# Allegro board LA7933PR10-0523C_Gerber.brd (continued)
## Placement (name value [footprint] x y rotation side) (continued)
CC90  -  [C_0402]  95.06 40.07 180 bottom
CC91  -  [C_D2]  94.84 21.81 270 bottom
CC92  -  [C_0402]  65.05 83.68 90 bottom
CD1  -  [C_0402]  131.1 14.75 270 top
CD2  -  [C_0402]  130.62 56.2 180 top
CD3  -  [C_0402]  130.62 51.88 180 top
CD4  -  [C_0402]  130.62 58.23 180 top
CD5  -  [C_0402]  130.62 60.01 180 top
CD6  -  [C_0402]  132.37 14.76 270 top
CD7  -  [C_0603]  130.86 48.32 180 top
CD8  -  [C_0603]  128.07 51.88 180 top
CD9  -  [C_0603]  130.86 44.77 180 top
CD10  -  [C_0603]  128.07 58.74 180 top
CD11  -  [C_0603]  128.07 56.2 180 top
CD12  -  [C_0603]  128.07 44.77 180 top
CD13  -  [C_0603]  128.07 48.32 180 top
CD14  -  [C_SX]  122.87 47.67 270 top
CD15  -  [C_0402]  130.62 62.29 180 top
CD16  -  [C_0402]  130.62 61.02 180 top
CD17  -  [C_0402]  130.62 87.44 180 top
CD18  -  [C_0402]  130.62 85.41 180 top
CD19  -  [C_0402]  130.62 84.39 180 top
CD20  -  [C_0402]  130.62 86.42 180 top
CD21  -  [C_0402]  127.83 82.36 180 top
CD22  -  [C_0402]  127.81 81.09 180 top
CD23  -  [C_0402]  130.66 22.45 90 bottom
CD24  -  [C_0402]  131.68 22.44 90 bottom
CD25  -  [C_0402]  130.62 58.23 180 bottom
CD26  -  [C_0402]  127.07 58.74 180 bottom
CD27  -  [C_0402]  130.62 56.2 180 bottom
CD28  -  [C_0402]  130.62 51.88 180 bottom
CD29  -  [C_0603]  127.3 56.2 180 bottom
CD30  -  [C_0603]  127.3 60.01 180 bottom
CD31  -  [C_0603]  127.3 51.88 180 bottom
CD32  -  [C_0603]  127.3 48.32 180 bottom
CD33  -  [C_0603]  127.3 44.77 180 bottom
CD34  -  [C_0603]  130.86 48.32 180 bottom
CD35  -  [C_0603]  130.86 44.77 180 bottom
CD36  -  [C_SX]  126.34 62.85 90 top
CD37  -  [C_0402]  127.1 82.07 270 bottom
CD38  -  [C_0402]  128.12 82.07 270 bottom
CD39  -  [C_0402]  130.78 82.07 270 bottom
CD40  -  [C_0402]  129.77 82.07 270 bottom
CD41  -  [C_0402]  130.86 62.29 180 bottom
CD42  -  [C_0402]  130.62 61.02 180 bottom
CD43  -  [C_0402]  130.88 79.82 180 bottom
CD44  -  [C_0402]  130.88 78.8 180 bottom
CD45  -  [C_0402]  162.41 22.45 90 top
CD46  -  [C_0402]  165.74 47.05 0 top
CD47  -  [C_0402]  161.68 47.05 0 top
CD48  -  [C_0402]  161.68 51.63 0 top
CD49  -  [C_0402]  161.4 22.45 90 top
CD50  -  [C_0402]  161.68 58.99 0 top
CD51  -  [C_0603]  161.69 45.02 0 top
CD52  -  [C_0603]  161.44 56.96 0 top
CD53  -  [C_0603]  165.5 53.66 0 top
CD54  -  [C_0603]  161.69 49.34 0 top
CD55  -  [C_0603]  165.5 56.96 0 top
CD56  -  [C_0603]  165.5 49.34 0 top
CD57  -  [C_0603]  165.5 45.02 0 top
CD58  -  [C_SX]  191.36 64.63 90 bottom
CD59  -  [C_0402]  164.69 82.07 270 top
CD60  -  [C_0402]  163.68 82.07 270 top
CD61  -  [C_0402]  162.66 82.07 270 top
CD62  -  [C_0402]  161.64 82.07 270 top
CD63  -  [C_0402]  161.69 61.79 0 top
CD64  -  [C_0402]  161.68 60.52 0 top
CD65  -  [C_0402]  161.64 79.02 270 top
CD66  -  [C_0402]  162.96 78.55 0 top
CD67  -  [C_0402]  162.41 22.45 90 bottom
CD68  -  [C_0402]  161.39 22.49 90 bottom
CD69  -  [C_0402]  165.74 51.63 0 bottom
CD70  -  [C_0402]  161.68 54.93 0 bottom
CD71  -  [C_0402]  161.68 47.05 0 bottom
CD72  -  [C_0402]  161.68 51.63 0 bottom
CD73  -  [C_0603]  165.5 49.34 0 bottom
CD74  -  [C_0603]  165.5 45.02 0 bottom
CD75  -  [C_0603]  161.69 49.34 0 bottom
CD76  -  [C_0603]  165.5 53.66 0 bottom
CD77  -  [C_0603]  161.69 56.83 0 bottom
CD78  -  [C_0603]  165.5 56.96 0 bottom
CD79  -  [C_0603]  161.69 45.02 0 bottom
CD80  -  [C_SX]  196.44 64.63 90 bottom
CD81  -  [C_0402]  163.97 80.85 270 bottom
CD82  -  [C_0402]  162.76 80.85 270 bottom
CD83  -  [C_0402]  161.85 80.85 270 bottom
CD84  -  [C_0402]  160.92 80.85 270 bottom
CD85  -  [C_0402]  161.69 61.79 0 bottom
CD86  -  [C_0402]  161.68 60.52 0 bottom
CD87  -  [C_0402]  161.64 78.99 270 bottom
CD88  -  [C_0402]  162.96 78.51 0 bottom
CE3  -  [C_0402]  182.9 88.66 0 top
CE4  -  [C_0402]  175.11 94.59 90 top
CE6  -  [C_0805]  78.84 132.45 90 bottom
CE8  -  [C_0402]  106.02 112.11 90 bottom
CE9  -  [C_0402]  100.94 112.11 90 bottom
CH1  -  [C_0402]  64.49 111.6 90 top
CH2  -  [C_0402]  13.43 114.49 180 top
CH3  -  [C_0402]  10.74 113.35 180 top
CH4  -  [C_0402]  18.23 111.82 180 bottom
CH5  -  [C_0402]  18.01 117.25 270 bottom
CH8  -  [C_0402]  8.7 125.79 180 bottom
CH18  -  [C_0402]  23.76 133.67 0 top
CH19  -  [C_0402]  26.74 133.67 180 top
CH20  -  [C_0402]  19.06 138.61 0 top
CH21  -  [C_0402]  23.32 139.79 180 top
CH22  -  [C_0402]  21.62 137.94 180 bottom
CH23  -  [C_0402]  20.35 139.81 0 top
CH30  -  [C_0603]  33.27 121.37 0 bottom
CH31  -  [C_0402]  31.12 121.1 0 bottom
CH32  -  [C_0402]  28.31 119.67 180 bottom
CH33  -  [C_0402]  29.86 114.03 270 bottom
CH34  -  [C_0402]  24.83 128.08 180 bottom
CH35  -  [C_0402]  24.83 128.97 180 bottom
CH36  -  [C_0603]  25.39 135.24 90 bottom
CH37  -  [C_0603]  23.82 134.95 90 bottom
CH40  -  [C_0603]  46.35 115.33 270 top
CH43  -  [C_0402]  26.01 120.29 90 bottom
CH44  -  [C_0603]  34.06 119.32 0 bottom
CH45  -  [C_0402]  31.31 116.35 0 bottom
CH46  -  [C_0402]  31.29 114.76 0 bottom
CH47  -  [C_0402]  33.12 112.45 270 bottom
CH48  -  [C_0402]  25.03 118.68 0 bottom
CH49  -  [C_0402]  35.88 113.35 180 bottom
CH50  -  [C_0402]  28.13 121.1 180 bottom
CH51  -  [C_0402]  44.9 121.07 0 top
CH52  -  [C_0402]  32.15 112.44 270 bottom
CH54  -  [C_0402]  27.28 101.12 270 top
CH55  -  [C_0402]  26.34 112.35 0 bottom
CH56  -  [C_0402]  23.93 116.1 180 bottom
CH57  -  [C_0402]  25.99 109.09 270 bottom
CH58  -  [C_0603]  46.35 116.7 90 top
CH59  -  [C_0402]  26.43 115.62 90 bottom
CH60  -  [C_0402]  24.97 115.05 270 bottom
CH61  -  [C_0402]  33.56 116.29 90 bottom
CH62  -  [C_0402]  33.6 114.76 270 bottom
CH63  -  [C_0402]  11.24 117.29 180 bottom
CH64  -  [C_0805]  33.32 97.35 270 top
CH65  -  [C_0805]  35.22 97.33 270 top
CH66  -  [C_0402]  24.97 115.93 90 bottom
CH67  -  [C_0402]  26.43 114.73 270 bottom
CH68  -  [C_0402]  28.05 116.29 0 bottom
CH69  -  [C_0402]  28.04 114.4 90 bottom
CH70  -  [C_0603]  14.09 114.55 180 bottom
CH71  -  [C_0603]  10.98 123.7 180 bottom
CH72  -  [C_0402]  27.99 113.11 0 bottom
CH73  -  [C_0603]  23.77 122.29 90 bottom
CH74  -  [C_0402]  25.5 123.02 270 bottom
CH75  -  [C_0402]  25.09 120.21 180 bottom
CH76  -  [C_0402]  32.61 101.12 270 top
CH77  -  [C_0402]  30.29 118.68 180 bottom
CH78  -  [C_0402]  24.01 112.6 180 bottom
CH79  -  [C_0402]  35.02 116.73 90 bottom
CH80  -  [C_0603]  33.88 101.11 270 top
CH81  -  [C_0402]  29.82 120.24 90 bottom
CH82  -  [C_0402]  28.44 111.67 0 bottom
CH83  -  [C_0402]  24.97 113.08 270 bottom
CH84  -  [C_0402]  25.42 110.87 270 bottom
CH85  -  [C_0603]  45.11 117.16 0 bottom
CH86  -  [C_0402]  41.62 108.72 270 bottom
CH87  -  [C_0402]  40.7 108.72 270 bottom
CH88  -  [C_0402]  17.2 114.57 0 bottom
CH89  -  [C_0402]  17.24 112.75 0 bottom
CH90  -  [C_0402]  17.2 113.64 0 bottom
CH91  -  [C_0402]  22.72 120.31 180 bottom
CH92  -  [C_0402]  39.05 127.54 90 bottom
CH93  -  [C_0402]  40.47 127.47 90 bottom
CH94  -  [C_B2]  37.69 132.55 270 top
CH95  -  [C_B2]  40.99 132.55 270 top
CH96  -  [C_0402]  31.25 119.57 0 bottom
CH97  -  [C_0402]  40.81 102.64 0 bottom
CH98  -  [C_0402]  7.94 120.71 180 bottom
CH99  -  [C_0402]  18.1 97.09 180 top
CH100  -  [C_0402]  36.68 96.8 270 bottom
CH101  -  [C_0402]  11.91 126.34 90 top
CH102  -  [C_0402]  6.48 102.17 0 top
CH103  -  [C_0402]  33.64 124.35 180 bottom
CH104  -  [C_0402]  33.53 125.79 0 bottom
CH105  -  [C_0805]  44.85 126.05 0 bottom
CH106  -  [C_0603]  33.56 132.21 90 bottom
CMOS1  -  [SHORTPADS]  143.86 92.52 90 bottom
D6  -  [BAT54CW_SOT323-3]  67.6 146.53 180 bottom
D7  -  [RB751VM-40TE-17_SOD323-2]  188.57 86.9 90 top
D8  -  [RB751VM-40TE-17_SOD323-2]  192.12 86.9 90 top
D9  -  [BAT1000-7-F_SOT23-3]  73.59 165.75 180 top
D10  -  [PESD5V0U2BT_SOT23-3]  53.95 166.15 0 top
D11  -  [PESD5V0U2BT_SOT23-3]  49.88 166.15 0 top
D12  -  [BAT1000-7-F_SOT23-3]  23.98 158.79 0 top
D13  -  [PESD5V0U2BT_SOT23-3]  13.33 133.67 90 top
D14  -  [IP4292CZ10-TBR_XSON10_2P5X1]  290.15 112.29 180 bottom
D15  -  [PESD5V0U2BT_SOT23-3]  296.77 122.01 0 bottom
D16  -  [IP4292CZ10-TBR_XSON10_2P5X1]  288.44 98.3 90 top
D17  -  [PESD5V0U2BT_SOT23-3]  288.64 93.79 90 top
D18  -  [RB751VM-40TE-17_SOD323-2]  190.35 86.9 90 top
D19  -  [RB751VM-40TE-17_SOD323-2]  198 150.91 0 bottom
D28  -  [RB751S40T1_SOD523-2]  298.68 110.35 270 bottom
D29  -  [RB751S40T1_SOD523-2]  186.92 101.66 270 bottom
D30  -  [RB751S40T1_SOD523-2]  177.01 86.42 90 bottom
D31  -  [RB751S40T1_SOD523-2]  191.87 102.87 270 bottom
D32  -  [RB751S40T1_SOD523-2]  117.19 126.11 90 top
D33  -  [PESD24VS2UT_SOT23-3]  75.79 135.22 0 bottom
D34  -  [RB751S40T1_SOD523-2]  249.47 69.15 180 bottom
D53  -  [RB751VM-40TE-17_SOD323-2]  69.95 147.67 270 bottom
D59  -  [RB751S40T1_SOD523-2]  234.35 60.77 0 bottom
D60  -  [RB751S40T1_SOD523-2]  228.45 63.76 270 bottom
D62  -  [RB751S40T1_SOD523-2]  235.56 63.76 270 bottom
D63  -  [RB751S40T1_SOD523-2]  229.97 63.76 270 bottom
D64  -  [RB751VM-40TE-17_SOD323-2]  82.87 140.02 0 top
D66  -  [RB751VM-40TE-17_SOD323-2]  80.91 136.46 180 top
D67  -  [RB751VM-40TE-17_SOD323-2]  82.87 136.46 0 top
D68  -  [RB751VM-40TE-17_SOD323-2]  85.1 130.24 180 top
D69  -  [RB751VM-40TE-17_SOD323-2]  82.87 138.24 0 top
D70  -  [RB751V-40GTE-17_SOD323-2]  37.4 163.64 0 top
D71  -  [RB751VM-40TE-17_SOD323-2]  83.16 138.78 270 bottom
D73  -  [PESD5V0U2BT_SOT23-3]  9.75 164.68 180 top
D86  -  [PESD5V0U2BT_SOT23-3]  4.67 121.88 180 top
D87  -  [PESD5V0U2BT_SOT23-3]  13.33 137.73 90 top
D90  -  [RB751S40T1_SOD523-2]  222.39 89.4 270 bottom
D103  -  [RB751S40T1_SOD523-2]  164.31 104.21 90 bottom
DH2  -  [RB751S40T1_SOD523-2]  11.21 118.68 180 bottom
DH3  -  [RB751S40T1_SOD523-2]  11.16 122.24 180 bottom
F3  -  [F_1206L150PR]  290.55 136.46 180 top
F4  -  [F_SMD1812P200TF]  32.78 158.8 180 top
F5  -  [F_SMD1812P200TF]  77.14 168.97 180 top
FD1  -  [FIDUCIAL_C40M80]  290.17 14.54 0 top
FD2  -  [FIDUCIAL_C40M80]  7.21 166.69 0 top
FD3  -  [FIDUCIAL_C40M80]  290.17 14.54 180 bottom
FD4  -  [FIDUCIAL_C40M80]  7.72 167.2 180 bottom
H1  -  [H_3P0]  296.49 169.7 0 top
H2  -  [H_3P6]  297.09 77.8 0 top
H3  -  [H_3P6]  220.49 77.8 0 top
H4  -  [H_3P0]  291.89 7.03 0 top
H5  -  [H_3P0]  270.89 87.13 0 top
H6  -  [H_3P6]  297.09 16.1 0 top
H7  -  [H_3P6]  220.49 16.1 0 top
H8  -  [H_5P2]  212.78 98.05 0 top
H9  -  [H_3P0]  198.39 26.03 0 top
H10  -  [H_3P0]  166.29 169.2 0 top
H11  -  [H_3P8]  136.89 170.77 0 top
H12  -  [H_3P8]  136.89 95.77 0 top
H13  -  [H_3P0]  123.29 7.43 0 top
H14  -  [H_3P0]  115.89 12.23 0 top
H15  -  [H_4P2]  104.19 87.4 0 top
H16  -  [H_4P2]  104.19 33.2 0 top
H17  -  [H_3P0]  60.49 167.7 0 top
H18  -  [H_4P2]  58.19 87.4 0 top
H19  -  [H_4P2]  55.19 33.2 270 top
H20  -  [H_3P0]  3.49 162.2 0 top
H21  -  [H_4P2N]  48.09 33.2 0 top
H22  -  [H_1P2]  73.37 157.91 180 bottom
H23  -  [H_1P2]  56.61 144.91 180 bottom
H24  -  [H_1P2]  41.61 157.91 180 bottom
H25  -  [H_1P2]  88.37 144.91 180 bottom
H26  -  [H_3P0X3P6]  293.29 159.2 90 top
JBT1  -  [ACES_50228-0127N-001_12P]  302.56 106.44 0 top
JCAM1  -  [ACES_50238-0207N-002_20P-T]  7.09 125.2 90 top
JCPU1  -  [TYCO_2134146-3_989P]  99.9 41.45 90 top
JCRT1  -  [SUYIN_070449HR015M221ZR_15P-T]  56.5 173.96 0 top
JDEG2  -  [ACES_87153-10411_10P]  211.91 108.94 90 top
JDIMM1  -  [TYCO_2-2013311-1_204P]  143.09 20.5 270 top
JDIMM2  -  [TYCO_2-2013290-1_204P]  134.89 20.5 270 bottom
JDIMM3  -  [TYCO_2-2013290-1_204P]  157.29 20.5 270 top
JDIMM4  -  [TYCO_2-2013289-1_204P]  149.09 20.5 270 bottom
JDOCK1  -  [JAE_WD2F144WB5R400_144P-T]  81.74 118.7 0 bottom
JDP1  -  [FOX_3V1121C-N1YD7-7H_20P-T]  293.78 150.25 90 top
JEDP1  -  [ACES_50398-04071-001_40P]  67.24 156.4 0 top
JESA1  -  [FOX_3Q38111-C35C5B-7H_11P-T]  14.49 170.97 180 top
JFAN1  -  [ACES_50271-0040N-001_4P]  11.15 84.9 90 bottom
JFAN2  -  [ACES_50271-0040N-001_4P]  225.91 79.82 315 bottom
JHDMI1  -  [FOX_QJ1119L-BT11-7H_19P-T]  27.95 168.29 180 top
JIO1  -  [FOX_QTS01401-A021-9H_140P-T]  31.01 45.55 90 top
JKB1  -  [AMPHE_G281010112CHR_10P]  80.75 111.25 0 top
JLOM1  -  [TYCO_2041333-1_13P]  84.22 162.27 180 top
JLVDS1  -  [ACES_50398-04071-001_40P]  82.24 143.39 0 top
JMINI1  -  [BELLW_80003-1121_52P]  99.84 140.25 90 bottom
JMINI2  -  [LCN_DAN08-52526-0100_52P]  202.29 90.36 180 bottom
JMINI3  -  [LCN_DAN08-52526-0100_52P]  169.84 165.18 0 bottom
JMINI4  -  [LCN_DAN08-52526-0100_52P]  9.64 157.75 0 bottom
JMXM1  -  [JAE_MM70-314-310B1-1-_310P-S]  197.69 173.27 270 top
JODD1  -  [FOX_LN21131-D008-9H_13P-T]  24.27 41.63 270 top
JPB1  -  [ACES_50228-0067N-001_6P]  276.49 90.98 180 top
JRTC1  -  [ACES_50271-0020N-001_2P]  51.92 99.76 270 bottom
JSATA1  -  [SUYIN_127043HB022M26GZL_22P-T]  200.42 35.91 90 top
JSATA2  -  [SUYIN_127043HB022M26GZL_22P-T]  64 32.16 0 top
JSIM1  -  [SUYIN_254070FB008S205ZL_8P]  263.56 28.9 180 bottom
JSPI1  -  [TYCO_1-2041070-6_16P]  48.97 104.26 270 bottom
JTAG1  -  [SHORTPADS]  167.74 157.8 90 top
JUSB1  -  [LOTES_AUSB0041-P001A_9P-T]  293.26 116.34 90 top
JUSB2  -  [LOTES_AUSB0041-P001A_9P-T]  293.26 93.25 90 top
JUSH1  -  [ACES_50554-02001-001_20P-T]  117.89 36.8 270 top
JWL1  -  [ACES_50228-0037N-001_3P-T]  283.62 7.24 180 top
JXDP1  -  [MOLEX_52435-2671_26P-T]  68.65 91.43 0 bottom
JXDP2  -  [SAMTE_BSH-030-01-L-D-A_60P]  76.56 108.59 180 top
L1  -  [MURAT_BLM18PG330SN1D_2P]  48.27 160.34 0 bottom
L2  -  [MURAT_BLM18PG330SN1D_2P]  52.08 160.34 0 bottom
L3  -  [MURAT_BLM18PG330SN1D_2P]  55.13 160.34 0 bottom
L4  -  [MURAT_BLM18AG121SN1D_L0603_2P]  66.39 166.85 90 top
L5  -  [MURAT_BLM18AG121SN1D_L0603_2P]  68.93 166.85 90 top
L10  -  [MURAT_DLW21SN121SQ2L_4P]  17.13 137.33 180 top
L11  -  [MURAT_DLW21SN121SQ2L_4P]  6.59 117.14 180 top
L19  -  [MURAT_DLW21SN900HQ2L_0805_4P]  33.8 162.41 90 top
L23  -  [MURAT_DLW21SN900HQ2L_0805_4P]  31.77 162.41 90 top
L24  -  [MURAT_DLW21SN900HQ2L_0805_4P]  29.74 162.41 90 top
L25  -  [MURAT_DLW21SN900HQ2L_0805_4P]  27.7 162.41 90 top
L29  -  [TAIYO_CBC2012T4R7M_2P]  118.71 159.7 180 top
L30  -  [DELTA_0603CS-120EJTS_2P]  118.97 150.06 270 top
L31  -  [DELTA_0603CS-120EJTS_2P]  120.5 150.06 270 top
L32  -  [DELTA_0603CS-120EJTS_2P]  123.54 150.06 270 top
L33  -  [DELTA_0603CS-120EJTS_2P]  122.02 150.06 270 top
L34  -  [DELTA_0603CS-120EJTS_2P]  125.07 150.06 270 top
L35  -  [DELTA_0603CS-120EJTS_2P]  126.59 150.06 270 top
L36  -  [DELTA_0603CS-120EJTS_2P]  128.12 150.06 270 top
L37  -  [DELTA_0603CS-120EJTS_2P]  129.64 150.06 270 top
L39  -  [MURAT_DLW21SN900SQ2L_0805_4P]  297.53 117.78 270 bottom
L40  -  [MURAT_DLW21SN900HQ2L_0805_4P]  288.54 110.39 270 bottom
L41  -  [CHENG_OCE2012120YZF_4P]  284.08 94.59 180 top
L42  -  [MURAT_DLW21SN900HQ2L_0805_4P]  290.57 110.39 270 bottom
L43  -  [MURAT_DLW21SN900HQ2L_0805_4P]  285.02 100.08 180 top
L44  -  [MURAT_DLW21SN900HQ2L_0805_4P]  285.04 97.75 180 top
L51  -  [MURAT_DLW21SN900SQ2L_0805_4P]  10.18 158.85 90 top
LH1  -  [TDK_GLFR1608T1R0M-LR_2P]  26.8 136.7 270 bottom
LH3  -  [TAIYO_LBR2012T100M_2P]  49.39 117.16 180 top
LH5  -  [TAIYO_LBR2012T100M_2P]  35.66 101.14 270 top
LH6  -  [TAIYO_LBR2012T100M_2P]  34.9 133.15 270 top
LH7  -  [TAIYO_LBR2012T100M_2P]  43.79 133.15 270 top
LH8  -  [TAIYO_HK1608R10J-T_L0603_2P]  46.22 127.83 180 bottom
ME1  -  [SHORTPADS]  142.59 92.52 90 bottom
NOREF  -  []  58.19 87.4 0 top
NOREF#2  -  []  104.19 33.2 0 top
NOREF#3  -  []  297.09 77.8 0 top
NOREF#4  -  []  296.49 169.7 0 top
NOREF#5  -  []  35.91 -39.81 0 top
NOREF#6  -  []  220.49 77.8 0 top
NOREF#7  -  []  104.19 87.4 0 top
NOREF#8  -  []  166.29 169.2 0 top
NOREF#9  -  []  220.49 16.1 0 top
NOREF#10  -  []  41.76 14.29 0 top
NOREF#11  -  []  291.89 7.03 0 top
NOREF#12  -  []  123.29 7.43 0 top
NOREF#13  -  []  270.89 87.13 0 top
NOREF#14  -  []  212.78 98.05 0 top
NOREF#15  -  []  136.89 170.77 0 top
NOREF#16  -  []  293.29 159.2 0 top
NOREF#17  -  []  55.19 33.2 0 top
NOREF#18  -  []  60.49 167.7 0 top
NOREF#19  -  []  41.61 157.91 0 top
NOREF#20  -  []  88.37 144.91 0 top
NOREF#21  -  []  236.83 31.46 0 top
NOREF#22  -  []  297.09 16.1 0 top
NOREF#23  -  []  265.28 27.1 0 top
NOREF#24  -  []  56.61 144.91 0 top
NOREF#25  -  []  3.49 162.2 0 top
NOREF#26  -  []  136.89 95.77 0 top
NOREF#27  -  []  198.39 26.03 0 top
NOREF#28  -  []  73.37 157.91 0 top
NOREF#29  -  []  90.46 104.14 0 top
NOREF#30  -  []  109.32 87.88 0 top
NOREF#31  -  []  115.89 12.23 90 top
NOREF#32  -  []  15.34 248.22 0 top
NOREF#33  -  []  125.7 111.13 180 bottom
NOREF#34  -  []  102.97 93.92 180 bottom
NOREF#35  -  []  112.41 81.81 180 bottom
PBATT1  -  [SUYIN_200045GR009M28QL_9P-T]  189.34 2.65 0 top
PC1  -  [C_25CE100AX]  188.97 51.12 270 top
PC2  -  [C_0603]  43.25 98.32 90 bottom
PC3  -  [C_0603]  191.11 6.21 90 top
PC4  -  [C_0402]  190.89 8.95 0 top
PC5  -  [C_0402]  210.41 7.72 90 top
PC6  -  [C_0402]  171.87 174.32 180 top
PC7  -  [C_0603]  130.2 123.25 0 top
PC8  -  [C_0603]  133.5 118.94 0 top
PC9  -  [C_0805]  15.91 75.43 180 top
PC10  -  [C_0603]  9.24 79.26 270 top
PC11  -  [C_0603]  14.33 60.69 270 top
PC12  -  [C_0603]  5.94 79.26 270 top
PC13  -  [C_0603]  7.47 79.26 270 top
PC14  -  [C_0805]  4.37 78.93 180 top
PC15  -  [C_0603]  17.75 71.95 0 top
PC16  -  [C_0402]  135.31 124.18 180 top
PC17  -  [C_0402]  159.37 174.54 90 top
PC18  -  [C_0402]  175.8 175.72 0 bottom
PC19  -  [C_0402]  161.38 173.62 0 top
PC20  -  [C_0402]  177.77 171.02 0 bottom
PC21  -  [C_0402]  175.84 168.15 0 bottom
PC30  -  [C_0805]  186.36 172 180 top
PC31  -  [C_0603]  186.1 173.75 180 top
PC100  -  [C_0603]  281.58 58.23 0 bottom
PC101  -  [C_0603]  275.82 64.28 90 bottom
PC102  -  [C_0402]  272.39 51.59 270 bottom
PC103  -  [C_0402]  279.79 53.4 0 bottom
PC104  -  [C_0805]  269.85 52.08 270 bottom
PC105  -  [C_0805]  281.58 61.79 0 bottom
PC106  -  [C_0402]  279.79 54.42 0 bottom
PC107  -  [C_0402]  271.37 51.59 270 bottom
PC108  -  [C_0805]  276.2 52.08 270 bottom
PC109  -  [C_0805]  274.17 52.08 270 bottom
PC110  -  [C_0603]  269.9 58.99 0 bottom
PC112  -  [C_MP6VLPS220MC4R2]  284.33 34.86 0 bottom
PC113  -  [C_MP6VLPS220MC4R2]  250.38 51.58 270 bottom
PC114  -  [C_0603]  275.69 43.29 90 bottom
PC115  -  [C_0603]  269.39 44.39 0 bottom
PC116  -  [C_0603]  277.93 53.91 180 bottom
PC117  -  [C_0805]  273.86 55.69 180 bottom
PC118  -  [C_0603]  275.23 55.69 0 bottom
PC119  -  [C_0603]  264.26 64.38 90 bottom
PC120  -  [C_0402]  277.25 65.34 0 bottom
PC121  -  [C_0402]  273.44 65.34 0 bottom
PC198  -  [C_0402]  269.51 46.4 90 bottom
PC199  -  [C_0402]  274.32 48.57 180 bottom
PC201  -  [C_0805]  219.58 32.45 0 bottom
PC202  -  [C_0805]  219.58 30.41 0 bottom
PC203  -  [C_0402]  214.43 35.51 180 bottom
PC204  -  [C_0402]  214.43 34.5 180 bottom
PC205  -  [C_0603]  227.6 43.24 180 bottom
PC206  -  [C_0805]  229.32 51.92 0 bottom
PC207  -  [C_0805]  229.32 49.88 0 bottom
PC208  -  [C_0603]  230.29 40.57 0 bottom
PC209  -  [C_MP2VLPS330MC4R2]  213.96 57.72 180 bottom
PC210  -  [C_0402]  232.62 49.63 90 bottom
PC211  -  [C_0603]  233.09 40.57 0 bottom
PC212  -  [C_0603]  228.46 31.64 180 bottom
PC213  -  [C_0402]  234.94 45.53 0 bottom
PC214  -  [C_0402]  239.01 46.55 0 bottom
PC215  -  [C_0402]  239.23 51.66 90 bottom
PC216  -  [C_0402]  239.01 37.91 0 bottom
PC217  -  [C_0402]  239.99 43.28 90 bottom
PC218  -  [C_0402]  244.31 43.28 90 bottom
PC299  -  [C_0402]  222.65 33.85 0 bottom
PC301  -  [C_0805]  106.35 16.45 180 bottom
PC302  -  [C_0402]  110.3 20.89 180 bottom
PC303  -  [C_0805]  98.27 15.38 270 bottom
PC304  -  [C_0805]  100.3 15.38 270 bottom
PC305  -  [C_0402]  107.98 22.06 90 bottom
PC306  -  [C_0603]  104.49 13.32 90 bottom
PC307  -  [C_0805]  212.71 71.76 180 bottom
PC308  -  [C_0402]  215.21 74.49 180 bottom
PC309  -  [C_0805]  202.31 75.55 90 bottom
PC310  -  [C_0805]  202.31 73.93 270 bottom
PC311  -  [C_0402]  210.92 76.74 90 bottom
PC312  -  [C_0603]  210.8 68.6 90 bottom
PC401  -  [C_0402]  12.93 144.3 270 bottom
PC402  -  [C_0402]  13.94 144.3 270 bottom
PC403  -  [C_0805]  11.53 144.79 270 bottom
PC404  -  [C_0805]  9.5 146.32 270 bottom
PC405  -  [C_0603]  4.93 150.38 270 top
PC406  -  [C_D2]  11.78 141.9 90 top
PC407  -  [C_0402]  5.43 156.18 90 top
PC408  -  [C_0603]  2.64 150.38 270 top
PC409  -  [C_0603]  11.01 139.15 90 bottom
PC499  -  [C_0402]  8.81 140.42 0 bottom
PC501  -  [C_0402]  61.37 16.76 90 bottom
PC502  -  [C_0402]  60.36 16.78 90 bottom
PC503  -  [C_0805]  62.86 16.68 90 bottom
PC504  -  [C_0805]  64.77 16.57 90 bottom
PC505  -  [C_0603]  63.42 23.71 270 bottom
PC506  -  [C_0603]  62.97 24.91 90 bottom
PC507  -  [C_0402]  56.46 22.42 180 bottom
PC508  -  [C_MP2VLPS330MC4R2]  71.73 26.73 0 bottom
PC509  -  [C_0603]  65.02 22.57 270 bottom
PC510  -  [C_0402]  51.94 25.72 270 bottom
PC511  -  [C_0402]  53.47 22.16 0 bottom
PC599  -  [C_0402]  65.62 19.67 180 bottom
PC601  -  [C_0603]  49.38 22.47 90 bottom
PC602  -  [C_0603]  52.21 22.29 180 bottom
PC603  -  [C_0603]  45.57 18.56 270 bottom
PC604  -  [C_0805]  38.75 29.76 0 bottom
PC605  -  [C_0805]  38.75 25.69 0 bottom
PC606  -  [C_0402]  47.03 27.23 270 bottom
PC607  -  [C_0805]  38.8 27.72 0 bottom
PC608  -  [C_0805]  38.75 31.79 0 bottom
PC609  -  [C_0402]  45.76 27.21 270 bottom
PC610  -  [C_0805]  44.5 27.72 180 bottom
PC611  -  [C_0805]  44.5 25.69 180 bottom
PC612  -  [C_0402]  57.25 18.32 270 bottom
PC613  -  [C_0402]  58.27 18.32 270 bottom
PC614  -  [C_0805]  55.73 16.88 90 bottom
PC615  -  [C_0805]  53.69 16.88 90 bottom
PC616  -  [C_0603]  38.07 14.33 270 bottom
PC617  -  [C_0402]  49.9 13.58 0 bottom
PC618  -  [C_0402]  49.9 12.62 0 bottom
PC619  -  [C_0402]  47.85 12.54 90 bottom
PC701  -  [C_0402]  25.63 80.62 90 bottom
PC702  -  [C_0402]  26.52 84.93 90 bottom
PC703  -  [C_0402]  25.47 87.44 180 top
PC704  -  [C_0402]  24.48 84.43 90 top
PC705  -  [C_0402]  24.52 85.41 0 bottom
PC706  -  [C_0402]  24.74 80.62 90 bottom
PC707  -  [C_0402]  22.17 81.09 180 bottom
PC708  -  [C_0402]  22.91 83.63 180 bottom
PC709  -  [C_0402]  22.17 82.11 180 bottom
PC710  -  [C_0603]  40.61 43.76 270 bottom
PC711  -  [C_0402]  23.21 83.16 90 top
PC712  -  [C_0603]  45.11 46.8 0 bottom
PC713  -  [C_0805]  39.27 49.94 90 top
PC714  -  [C_0805]  48.04 46.71 180 top
PC715  -  [C_0805]  49.5 48.99 90 bottom
PC716  -  [C_0603]  43.66 48.93 90 bottom
PC717  -  [C_0402]  40.23 48.91 90 bottom
PC718  -  [C_0402]  19.97 82.93 180 bottom
PC719  -  [C_0402]  22.17 82.11 180 top
PC720  -  [C_0402]  22.17 81.09 180 top
PC721  -  [C_0603]  40.11 53.02 270 bottom
PC722  -  [C_0603]  32.13 78.96 0 top
PC723  -  [C_0603]  29.13 79.44 180 bottom
PC724  -  [C_EEEFK1E101YP]  27.82 57.04 90 top
PC725  -  [C_EEEFK1E101YP]  43.32 40.96 0 top
PC726  -  [C_EEEFK1E101YP]  20.47 59.86 90 top
PC727  -  [C_0805]  34.91 71.07 90 top
PC728  -  [C_0805]  35.05 76.16 90 top
PC729  -  [C_0805]  36.47 76.31 0 bottom
PC730  -  [C_0402]  37.09 68.9 0 bottom
PC731  -  [C_0603]  36.85 70.17 0 bottom
PC732  -  [C_0402]  19.88 77.03 180 top
PC733  -  [C_0402]  22.25 72.93 270 bottom
PC734  -  [C_0603]  33.58 81.09 180 top
PC735  -  [C_0402]  29.03 73.97 270 top
PC736  -  [C_0402]  28.24 76.85 180 bottom
PC737  -  [C_0603]  41.63 75.47 90 bottom
PC738  -  [C_0402]  23.21 72.93 270 top
PC739  -  [C_0402]  24.23 72.93 270 top
PC740  -  [C_0402]  18.9 78.9 270 top
PC741  -  [C_0402]  28.55 75.72 270 bottom
PC742  -  [C_0402]  25.25 72.93 270 top
PC743  -  [C_0402]  26.19 72.98 270 top
PC744  -  [C_0805]  34.92 65.23 90 top
PC745  -  [C_0805]  34.94 59.32 90 top
PC746  -  [C_0805]  36.6 64.45 0 bottom
PC747  -  [C_0603]  36 61.23 0 bottom
PC748  -  [C_0402]  35.82 58.79 0 bottom
PC749  -  [C_0402]  27.4 71.11 180 top
PC750  -  [C_0402]  30.33 73.44 270 bottom
PC751  -  [C_0402]  28.32 73.45 270 bottom
PC752  -  [C_0402]  29.31 73.44 270 bottom
PC753  -  [C_0402]  26.29 76.84 90 bottom
PC754  -  [C_0603]  33.55 77.36 180 top
PC755  -  [C_0402]  25.25 71.98 90 bottom
PC756  -  [C_0402]  23.21 71.98 90 bottom
PC757  -  [C_0603]  41.76 64.81 90 bottom
PC758  -  [C_0805]  36.17 92.2 0 top
PC759  -  [C_0805]  36.35 88.5 0 bottom
PC761  -  [C_0603]  36.89 90.4 0 bottom
PC762  -  [C_0402]  36.71 84.89 0 bottom
PC763  -  [C_0603]  33.53 87.35 270 top
PC764  -  [C_0603]  28.6 90.36 0 top
PC765  -  [C_0603]  40.94 90.16 180 bottom
PC766  -  [C_0805]  36.42 81.9 0 bottom
PC767  -  [C_0805]  34.94 83.06 90 top
PC769  -  [C_0603]  36.47 83.68 0 bottom
PC770  -  [C_0402]  37.18 78.34 0 bottom
PC771  -  [C_0603]  28.55 85.61 270 top
PC772  -  [C_0603]  41.63 83.88 270 bottom
PC791  -  [C_0402]  51.03 52.61 90 bottom
PC792  -  [C_0402]  45.07 53.75 90 bottom
PC793  -  [C_0402]  43.13 72.06 90 bottom
PC794  -  [C_0402]  41.84 69.17 270 bottom
PC795  -  [C_0402]  42.95 58.44 270 bottom
PC796  -  [C_0402]  41.81 61.29 90 bottom
PC797  -  [C_0402]  41.34 86.11 0 bottom
PC798  -  [C_0402]  41.9 81.16 270 bottom
PC901  -  [C_0603]  6.45 100.85 270 top
PC902  -  [C_0402]  199.11 44.93 90 bottom
PC903  -  [C_0603]  196.7 44.69 90 bottom
PC904  -  [C_0402]  171.33 37.4 0 top
PC905  -  [C_0402]  173.11 36.13 0 top
PC906  -  [C_0402]  173.36 37.4 0 top
PC907  -  [C_0805]  181.25 33.85 0 top
PC908  -  [C_0603]  175.61 37.45 90 top
PC909  -  [C_0402]  171.52 33.85 180 top
PC910  -  [C_0603]  181.13 39.31 0 top
PC911  -  [C_0603]  181.51 32.07 0 top
PC912  -  [C_0402]  198.09 44.93 90 bottom
PC913  -  [C_0603]  190.85 44.56 90 bottom
PC914  -  [C_0805]  194.66 44.31 90 bottom
PC915  -  [C_0805]  192.63 44.31 90 bottom
PC916  -  [C_0402]  176.38 26.95 270 top
PC917  -  [C_0402]  179.93 37.44 90 top
PC918  -  [C_0402]  168.28 28 0 top
PC919  -  [C_0402]  187.3 42.7 270 bottom
PC920  -  [C_0402]  168.25 30.26 270 top
PC921  -  [C_0402]  169.26 30.26 270 top
PC922  -  [C_0402]  173.84 26.95 270 top
PC923  -  [C_0402]  169.26 31.34 90 top
PC924  -  [C_0603]  172.01 32.58 180 top
PC925  -  [C_0603]  195.17 33.01 90 bottom
PC926  -  [C_0402]  170.57 28 0 top
PC927  -  [C_0402]  168.25 31.34 90 top
PC928  -  [C_0402]  171.52 25.97 180 top
PC929  -  [C_0603]  189.38 22.92 0 top
PC930  -  [C_0805]  189.38 26.73 0 top
PC931  -  [C_0805]  189.38 28.77 0 top
PC932  -  [C_0805]  189.38 24.7 0 top
PC933  -  [C_0402]  184.22 30.8 180 top
PC934  -  [C_0603]  181.71 30.24 270 top
PC935  -  [C_0402]  183.27 27.75 0 top
PC936  -  [C_0402]  236.43 16 0 bottom
PC937  -  [C_0402]  236.43 14.99 0 bottom
PC938  -  [C_0402]  229.76 21.35 180 bottom
PC939  -  [C_0402]  229.76 20.08 180 bottom
PC940  -  [C_0402]  237.89 22.61 180 bottom
PC941  -  [C_0402]  239.49 21.07 0 bottom
PC942  -  [C_0402]  249.06 18.05 180 bottom
PC999  -  [C_0402]  193.91 34.39 90 bottom
PC1001  -  [C_0805]  133.65 105.04 180 bottom
PC1002  -  [C_0402]  143.36 107.22 270 bottom
PC1003  -  [C_0603]  144.75 107.2 270 bottom
PC1004  -  [C_0805]  179.12 20.38 180 top
PC1005  -  [C_0603]  200.51 15.05 0 bottom
PC1006  -  [C_0603]  173.84 66.82 270 top
PC1007  -  [C_0603]  175.61 66.82 270 top
PC1008  -  [C_0603]  181.76 70.68 0 top
PC1009  -  [C_0402]  182 71.95 0 top
PC1101  -  [C_0805]  80.92 57.72 0 top
PC1102  -  [C_0805]  77.44 52.52 0 bottom
PC1103  -  [C_0805]  80.92 55.56 0 top
PC1104  -  [C_0805]  59.99 47.74 180 top
PC1105  -  [C_0805]  77.44 54.42 0 bottom
PC1106  -  [C_0805]  77.44 66.99 0 bottom
PC1107  -  [C_0805]  77.44 56.58 0 bottom
PC1108  -  [C_0805]  77.44 58.74 0 bottom
PC1109  -  [C_0805]  77.44 60.9 0 bottom
PC1110  -  [C_0805]  77.44 63.06 0 bottom
PC1111  -  [C_0805]  77.44 65.09 0 bottom
PC1112  -  [C_0805]  82.02 66.05 270 top
PC1113  -  [C_0805]  83.92 66.05 270 top
PC1114  -  [C_0805]  82.02 66.05 270 bottom
PC1115  -  [C_0805]  83.92 66.05 270 bottom
PC1116  -  [C_0805]  86.21 81.9 90 top
PC1117  -  [C_0805]  80.11 81.9 90 top
PC1118  -  [C_0805]  79.22 79.87 90 bottom
PC1119  -  [C_0805]  78.08 81.9 90 top
PC1120  -  [C_0805]  79.37 58.74 180 top
PC1121  -  [C_0805]  82.85 59.88 180 top
PC1122  -  [C_0805]  58.06 63.61 0 top
PC1123  -  [C_0805]  82.85 62.04 180 top
PC1124  -  [C_0805]  58.06 52.18 0 top
PC1125  -  [C_0805]  88.44 52.13 180 bottom
PC1126  -  [C_0805]  89.05 24.96 0 bottom
PC1127  -  [C_0805]  89.05 26.99 0 bottom
PC1128  -  [C_0805]  89.05 29.02 0 bottom
PC1129  -  [C_0805]  85.39 26.99 180 bottom
PC1130  -  [C_0805]  85.39 29.02 180 bottom
PC1131  -  [C_0805]  88.8 38.16 0 bottom
PC1132  -  [C_0805]  85.65 36.13 180 bottom
PC1133  -  [C_0805]  85.65 38.16 180 bottom
PC1134  -  [C_0805]  85.39 24.96 180 bottom
PC1135  -  [C_0805]  88.8 36.13 0 bottom
PC1136  -  [C_0805]  83.67 79.87 90 bottom
PC1137  -  [C_0805]  81.63 79.87 90 bottom
PC1138  -  [C_0805]  82.14 81.9 90 top
PC1139  -  [C_0805]  84.17 81.9 90 top
PC1140  -  [C_0805]  77.06 79.87 90 bottom
PC1141  -  [C_0805]  85.83 79.87 90 bottom
PC1144  -  [C_0805]  58.06 54.47 0 top
PC1145  -  [C_0805]  58.06 56.75 0 top
PC1146  -  [C_0805]  58.06 59.04 0 top
PC1147  -  [C_0805]  58.06 61.33 0 top
PC1148  -  [C_0805]  58.06 65.9 0 top
PC1149  -  [C_0805]  88.44 60.52 180 top
PC1150  -  [C_0805]  88.44 52.13 180 top
PC1151  -  [C_0805]  88.44 54.29 180 bottom
PC1152  -  [C_0805]  88.44 56.45 180 bottom
PC1153  -  [C_0805]  88.44 54.29 180 top
PC1154  -  [C_0805]  88.44 58.48 180 bottom
PC1155  -  [C_0805]  88.44 56.45 180 top
PC1156  -  [C_0805]  88.44 58.48 180 top
PC1157  -  [C_D2]  85.29 87.06 0 top
PC1158  -  [C_D2]  81.1 87.06 180 top
PC1161  -  [C_0805]  79.37 60.9 180 top
PC1162  -  [C_0805]  79.37 63.06 180 top
PC1163  -  [C_0805]  79.37 65.22 180 top
PC1164  -  [C_0805]  79.37 52.52 180 top
PC1165  -  [C_0805]  79.37 54.42 180 top
PC1166  -  [C_D2]  80.36 21.81 270 bottom
PC1167  -  [C_D2]  85.19 21.81 270 bottom
PC1168  -  [C_D2]  90.02 21.81 270 bottom
PC1169  -  [C_0805]  79.37 56.58 180 top
PC1170  -  [C_0805]  58.06 49.77 0 top
PC1173  -  [C_D2]  82.78 61.15 270 bottom
PC1174  -  [C_D2]  59.05 66.28 180 bottom
PC1175  -  [C_D2]  59.05 61.45 180 bottom
PC1176  -  [C_D2]  59.05 56.75 180 bottom
PC1177  -  [C_D2]  60.83 51.93 180 bottom
PC1178  -  [C_D2]  60.83 47.1 180 bottom
PD1  -  [RB715FGT106_UMD3]  44.69 98.97 270 bottom
PD2  -  [PESD24VS2UT_SOT23-3]  194.92 8.47 180 top
PD3  -  [PESD24VS2UT_SOT23-3]  200 8.47 180 top
PD5  -  [SDMK0340L-7-F_SOD323-2]  204.06 9.11 270 top
PD7  -  [DA204U_SOT323-3]  6.45 74.23 0 bottom
PD100  -  [RB751V_SOD323-2]  282.29 56.2 180 bottom
PD901  -  [SBR3A40SA-13_SMA2]  11.35 87.01 0 top
PD902  -  [RB717F_SOT323-3]  181.27 35.75 90 bottom
PD903  -  [RB751V-40_SOD323-2]  178.97 40.7 180 top
PD1001  -  [PDS5100H-13_POWERDI5-3]  140.05 106.84 90 bottom
PD1002  -  [PDS5100H-13_POWERDI5-3]  186.36 18.63 270 bottom
PH701  -  [R_0402]  53.38 85.31 270 top
PH702  -  [R_0402]  41.75 91.71 0 top
PH703  -  [R_0402]  38.93 54.72 180 top
PH704  -  [R_0402]  53.19 70.18 270 top
PJP28  -  [JUMP_43X39]  170.53 137.53 90 top
PJP29  -  [JUMP_43X39]  244.75 81.34 0 bottom
PJP30  -  [JUMP_43X79]  289.32 58.48 180 bottom
PJP31  -  [JUMP_43X79]  14.37 159.83 180 top
PJP32  -  [JUMP_43X79]  26.77 29.49 90 bottom
PJP33  -  [JUMP_43X79]  195.68 57.51 270 top
PJP34  -  [JUMP_43X39]  261.85 66.97 0 bottom
PJP35  -  [JUMP_43X39]  254.81 66.87 180 bottom
PJP70  -  [JUMP_43X39]  28.29 96.53 270 bottom
PJP77  -  [JUMP_43X39]  174.62 108.7 270 top
PJP78  -  [JUMP_43X118]  181.82 172.8 180 top
PJP79  -  [JUMP_43X118]  179.79 168.44 90 top
PJP102  -  [JUMP_43X118]  257.66 41.76 270 bottom
PJP103  -  [JUMP_43X118]  253.34 41.76 270 bottom
PJP104  -  [JUMP_43X118]  285.09 28.05 270 bottom
PJP105  -  [JUMP_43X118]  291.95 28.05 270 bottom
PJP201  -  [JUMP_43X118]  215.22 30.65 0 bottom
PJP202  -  [JUMP_43X118]  210.32 57.45 180 bottom
PJP203  -  [JUMP_43X118]  210.21 63.04 180 bottom
PJP204  -  [JUMP_43X39]  226.1 49.61 180 bottom
PJP205  -  [JUMP_43X79]  230.61 55.27 270 bottom
PJP301  -  [JUMP_43X79]  99.46 23.71 180 bottom
PJP302  -  [JUMP_43X79]  200.07 73.98 180 bottom
PJP401  -  [JUMP_43X118]  15.81 145.05 0 bottom
PJP402  -  [JUMP_43X118]  16.78 142.18 180 top
PJP501  -  [JUMP_43X118]  62.84 13.48 90 bottom
PJP502  -  [JUMP_43X118]  76.6 25.79 180 bottom
PJP601  -  [JUMP_43X118]  56.49 14.54 270 bottom
PJP602  -  [JUMP_43X118]  40.7 35.34 0 bottom
PJP603  -  [JUMP_43X39]  52.68 12.81 90 bottom
PJP902  -  [JUMP_43X39]  171.55 35.17 90 top
PJPDC1  -  [ACES_50290-01101-001_11P]  8.74 74.87 270 top
PL1  -  [CHT_C8BBPH853025_2P]  190.85 53.15 90 bottom
PL2  -  [TAIYO_FBMJ4516HS720NT_2P]  189.02 9.2 180 top
PL3  -  [MURAT_BLM18BD102SN1D_L0603_2P]  2.8 71.95 0 bottom
PL4  -  [CHT_C8BBPH853025_2P]  15.03 66.81 90 top
PL6  -  [TAIYO_FBMJ4516HS720NT_2P]  189.02 6.96 180 top
PL100  -  [CYNTE_PCMB053T-1R0MS_2P]  269.05 56.2 180 bottom
PL102  -  [TOKO_FDV0630-3R3M-P3_2P]  262.18 49.85 180 bottom
PL103  -  [TOKO_FDSD0630-H-2R2M-P3_2P]  282.8 41.33 90 bottom
PL201  -  [CYNTE_PCMC104T-1R0MN_2P]  212.33 46.81 0 bottom
PL301  -  [TAI-T_HCB1608KF-121T3_L0603_2P]  106.27 13.11 90 bottom
PL302  -  [TAIYO_NRS4018T1R0NDGJ_2P]  102.16 18.97 180 bottom
PL303  -  [TAI-T_HCB1608KF-121T3_L0603_2P]  214.51 70.17 180 bottom
PL304  -  [TAIYO_NRS4018T1R0NDGJ_2P]  207.79 74.74 180 bottom
PL401  -  [TAI-T_VMPI0703AR-1R0M-Z01_2P]  5.64 146.33 270 top
PL501  -  [TAI-T_VMPI0703AR-1R0M-Z01_2P]  74.39 15.04 90 bottom
PL601  -  [TAI-T_VMPI0703AR-1R0M-Z01_2P]  41.19 16.81 90 bottom
PL701  -  [NEC_MPC0740LR42C_2P]  51.21 59.29 180 top
PL702  -  [NEC_MPC0740LR42C_2P]  51.21 73.52 180 top
PL703  -  [NEC_MPC0740LR42C_2P]  51.21 66.41 180 top
PL704  -  [NEC_MPC0740LR42C_2P]  51.21 88.25 180 top
PL705  -  [NEC_MPC0740LR42C_2P]  51.21 80.88 180 top
PL710  -  [KC_FBMA-L11-453215-121LMA90T_2]  31.33 53.2 0 top
PL901  -  [CYNTE_PCMB053T-1R0MS_2P]  198.73 41.93 270 bottom
PL902  -  [TOKO_FDVE1040-H-5R6M-P3_2P]  189.58 35.17 90 top
PQ1  -  [FDN338P_NL_SOT23-3]  206.91 6.39 0 top
PQ2  -  [FDV301N_NL_SOT23-3]  4.16 69.69 0 bottom
PQ3  -  [MMST3904-7-F_SOT323-3]  3.4 60.07 0 bottom
PQ4  -  [TP0610K-T1-E3_SOT23-3]  130.91 118.91 0 top
PQ5  -  [SI7447DP_SO8_5P]  11.61 77.89 0 top
PQ7  -  [SSM3K7002FU_SC70-3]  134.58 120.95 0 top
PQ101  -  [SI7326DN-T1-E3_PAK1212-8]  280.88 52.11 270 bottom
PQ102  -  [SI7326DN-T1-E3_PAK1212-8]  265.17 50.38 90 bottom
PQ103  -  [SI7326DN-T1-E3_PAK1212-8]  275.49 46.52 90 bottom
PQ104  -  [SI7326DN-T1-E3_PAK1212-8]  268.04 48.45 270 bottom
PQ105  -  [DTC115EUA_SC70-3]  267.6 65.09 270 bottom
PQ106  -  [2N7002DW-T-R7_SOT363-6]  270.75 63.97 180 bottom
PQ201  -  [FDMS7696A_POWER56-8-5]  216.82 40.54 0 bottom
PQ202  -  [FDMS0309S_POWER56-8-5]  226.31 35.21 180 bottom
PQ204  -  [2N7002DW-T-R7_SOT363-6]  239.91 48.02 180 bottom
PQ205  -  [2N7002DW-T-R7_SOT363-6]  240 39.89 180 bottom
PQ401  -  [SI7326DN-T1-E3_PAK1212-8]  4.56 144.87 90 bottom
PQ402  -  [SI7326DN-T1-E3_PAK1212-8]  7.45 143.17 270 bottom
PQ501  -  [SI7326DN-T1-E3_PAK1212-8]  69.8 15.79 270 bottom
PQ502  -  [SI7326DN-T1-E3_PAK1212-8]  66.91 17.61 90 bottom
PQ503  -  [SSM3K7002FU_SC70-3]  53.69 23.5 180 bottom
PQ701  -  [CSD86350Q5D_SON8]  47.55 48.73 0 top
PQ702  -  [CSD86350Q5D_SON8]  41.76 48.75 0 top
PQ703  -  [CSD86350Q5D_SON8]  36.52 71.54 270 top
PQ704  -  [CSD86350Q5D_SON8]  36.65 77.38 270 top
PQ705  -  [CSD86350Q5D_SON8]  36.52 65.69 270 top
PQ706  -  [CSD86350Q5D_SON8]  36.52 59.73 270 top
PQ707  -  [CSD86350Q5D_SON8]  36.52 89.57 270 top
PQ708  -  [CSD86350Q5D_SON8]  36.52 83.47 270 top
PQ901  -  [SI7447DP_SO8_5P]  7.77 87.19 180 top
PQ902  -  [NTR4502PT1G_SOT23-3]  9.75 95.42 0 top
PQ903  -  [NTR4502PT1G_SOT23-3]  5.43 95.29 0 top
PQ904  -  [NTGD4161PT1G_TSOP6]  112.21 119.63 270 top
PQ905  -  [SIR472DP-T1-GE3_POWERPAK8-5]  189.45 39.05 90 bottom
PQ906  -  [SI7716ADN-T1-GE3_POWERPAK8-5]  192.29 37.12 270 bottom
PQ907  -  [SI7447DP_SO8_5P]  135.61 107.11 180 bottom
PQ908  -  [2N7002DW-T-R7_SOT363-6]  241.11 17.5 90 bottom
PQ909  -  [SSM3K7002FU_SC70-3]  241.64 20.89 90 bottom
PQ910  -  [SSM3K7002FU_SC70-3]  244.99 15.25 90 bottom
PQ1002  -  [SI4835DDY-T1-E3_SO8]  185.67 21.27 270 top
PQ1003  -  [SI7447DP_SO8_5P]  185.58 15.43 270 top
PQ1004  -  [SI7447DP_SO8_5P]  189.63 20.78 0 bottom
PQ1005  -  [2N7002DW-T-R7_SOT363-6]  163.83 175.16 270 top
PR1  -  [R_0402]  49.47 99.89 180 bottom
PR2  -  [R_0402]  202.54 9.43 270 top
PR3  -  [R_0402]  192.38 6.45 90 top
PR4  -  [R_0402]  202.54 6.45 90 top
PR5  -  [R_0402]  197.46 6.45 90 top
PR6  -  [R0402_0OHM]  209.4 8.67 270 top
PR7  -  [R_0402]  5.98 71.31 0 bottom
PR8  -  [R_0402]  5.72 76.52 0 bottom
PR9  -  [R_0402]  6.67 75.5 180 bottom
PR10  -  [R_0402]  5.18 58.17 90 bottom
PR11  -  [R_0402]  2.93 65.6 0 bottom
PR12  -  [R_0402]  6.17 59.12 270 bottom
PR13  -  [R_0402]  3.88 61.41 180 bottom
PR14  -  [R_0402]  170.94 172.39 90 top
PR15  -  [R_0402]  130.44 124.78 0 top
PR16  -  [R_0402]  14.97 74 0 top
PR17  -  [R_0402]  132.8 122.94 90 top
PR18  -  [R_0402]  3.88 77.53 180 top
PR19  -  [R_0805]  17.75 70.17 0 top
PR20  -  [R_0402]  17.04 75.08 270 top
PR21  -  [R_0402]  134.36 125.11 0 top
PR22  -  [R_0402]  17.98 75.08 270 top
PR23  -  [R0402_0OHM]  134.36 126.04 0 top
PR24  -  [R_0402]  171.84 172.39 90 top
PR25  -  [R_1206_4P-D]  176.8 169.04 180 top
PR26  -  [R_0402]  177.78 170.09 0 bottom
PR27  -  [R_0402]  178.73 169.13 180 bottom
PR28  -  [R_0402]  170.86 175.43 0 top
PR29  -  [R_0402]  161.38 174.55 0 top
PR30  -  [R_0402]  173 173.33 90 top
PR31  -  [R_0402]  175.83 173.78 90 bottom
PR101  -  [R_0402]  278.2 64.33 180 bottom
PR102  -  [R_0402]  274.39 64.33 180 bottom
PR103  -  [R_0402]  278.2 66.36 180 bottom
PR104  -  [R_0402]  274.39 66.36 180 bottom
PR105  -  [R0402_0OHM]  282.77 63.31 180 bottom
PR106  -  [R_0402]  279.25 65.31 270 bottom
PR107  -  [R_0402]  272.39 64.36 90 bottom
PR108  -  [R_0603]  283.01 60.01 180 bottom
PR109  -  [R_0603]  271.32 60.77 180 bottom
PR110  -  [R_1206]  277.72 44.9 270 bottom
PR111  -  [R_1206]  264.51 44.39 0 bottom
PR112  -  [R_0402]  278.01 55.18 0 bottom
PR113  -  [R_0402]  278.01 56.2 0 bottom
PR114  -  [R_0402]  271.09 62.29 180 bottom
PR115  -  [R_0402]  266.77 61.53 180 bottom
PR117  -  [R_0402]  268.07 62.51 270 bottom
PR118  -  [R0402_0OHM]  266.77 62.55 180 bottom
PR201  -  [R_0603]  226.17 44.87 0 bottom
PR202  -  [R_0402]  232.57 42 180 bottom
PR203  -  [R_1206]  228.84 37.28 270 bottom
PR204  -  [R_0603]  231.84 38.66 0 bottom
PR205  -  [R_0402]  235.89 43.5 180 bottom
PR206  -  [R0402_0OHM]  234.66 50.58 270 bottom
PR208  -  [R_0402]  243.29 43.28 90 bottom
PR209  -  [R_0402]  235.89 44.51 180 bottom
PR210  -  [R_0402]  235.89 47.56 180 bottom
PR211  -  [R_0402]  241.26 44.23 270 bottom
PR213  -  [R_0402]  237.2 48.04 270 bottom
PR214  -  [R0402_0OHM]  235.89 48.58 180 bottom
PR215  -  [R_0402]  242.28 43.28 90 bottom
PR216  -  [R_0402]  237.2 49.12 90 bottom
PR217  -  [R_0402]  239.01 45.53 0 bottom
PR218  -  [R_0402]  241.26 42.19 270 bottom
PR219  -  [R_0402]  237.23 51.63 0 bottom
PR220  -  [R_0402]  240.24 51.66 90 bottom
PR221  -  [R_0402]  237.2 38.89 270 bottom
PR222  -  [R_0402]  237.2 40.74 90 bottom
PR223  -  [R_0402]  236.99 43.22 0 bottom
PR224  -  [R_0402]  239.01 36.89 0 bottom
PR225  -  [R_0402]  238.97 43.28 90 bottom
PR226  -  [R0402_0OHM]  235.89 46.55 180 bottom
PR301  -  [R_0402]  103.63 23 270 bottom
PR302  -  [R_1206]  102.59 15.69 270 bottom
PR303  -  [R_0402]  110.3 19.88 180 bottom
PR304  -  [R_0402]  104.75 23 270 bottom
PR305  -  [R_0402]  106.86 22.09 90 bottom
PR306  -  [R_0402]  109.35 18.86 0 bottom
PR307  -  [R0402_0OHM]  105.79 23 270 bottom
PR308  -  [R_0402]  209.9 77.69 270 bottom
PR309  -  [R_1206]  208.56 71.31 270 bottom
PR310  -  [R_0402]  215.21 73.47 180 bottom
PR311  -  [R0402_0OHM]  213.21 77.69 270 bottom
PR312  -  [R_0402]  212.09 76.82 90 bottom
PR313  -  [R_0402]  214.26 75.5 0 bottom
PR314  -  [R_0402]  214.22 77.79 270 bottom
PR401  -  [R_0402]  8.18 154.93 180 top
PR402  -  [R_0603]  6.7 150.38 270 top
PR403  -  [R_0402]  7.47 157.13 270 top
PR404  -  [R0402_0OHM]  6.45 157.13 270 top
PR405  -  [R_1206]  4.57 139.18 0 bottom
PR406  -  [R_0402]  2.39 156.18 90 top
PR407  -  [R_0402]  3.4 157.13 270 top
PR408  -  [R_0402]  4.42 157.13 270 top
PR501  -  [R_0402]  58.72 21.12 180 bottom
PR502  -  [R_0603]  61.62 20.89 0 bottom
PR503  -  [R_0402]  55.51 20.38 0 bottom
PR504  -  [R0402_0OHM]  55.51 21.4 0 bottom
PR505  -  [R_1206]  69.55 21.73 180 bottom
PR506  -  [R_0402]  58.06 26.53 0 bottom
PR508  -  [R_0402]  55.51 23.43 0 bottom
PR509  -  [R0402_0OHM]  54.42 21.15 180 bottom
PR510  -  [R0402_0OHM]  54.24 26.73 0 bottom
PR511  -  [R_0402]  55.51 25.46 0 bottom
PR512  -  [R_0402]  56.46 24.45 180 bottom
PR514  -  [R_0402]  52.03 28.24 270 bottom
PR515  -  [R_0402]  54.24 27.75 0 bottom
PR601  -  [R_0402]  47.73 23.65 270 bottom
PR602  -  [R_0402]  49.23 25.96 270 bottom
PR603  -  [R0402_0OHM]  48.29 25.96 270 bottom
PR604  -  [R_0402]  46.71 23.65 270 bottom
PR605  -  [R_0402]  50.7 23.61 0 bottom
PR606  -  [R0402_0OHM]  45.69 22.7 90 bottom
PR607  -  [R_0603]  45.57 21.35 270 bottom
PR608  -  [R_1206]  42.77 13.83 180 bottom
PR609  -  [R_0402]  44.8 12.54 90 bottom
PR610  -  [R_0402]  46.84 12.54 90 bottom
PR611  -  [R0402_0OHM]  45.82 13.49 270 bottom
PR612  -  [R_0402]  48.87 13.49 270 bottom
PR613  -  [R0402_0OHM]  49.18 26.96 0 bottom
PR614  -  [R0402_0OHM]  49.18 27.98 0 bottom
PR701  -  [R_0402]  25.47 84.39 180 bottom
PR702  -  [R_0402]  25.5 84.43 90 top
PR703  -  [R_0402]  25.47 86.42 180 bottom
PR704  -  [R_0402]  24.52 86.42 0 top
PR705  -  [R_0402]  25.47 87.44 180 bottom
PR706  -  [R_0402]  22.17 79.06 180 bottom
PR707  -  [R_0402]  27.02 84.43 90 top
PR708  -  [R_0402]  22.17 80.07 180 bottom
PR709  -  [R_0603]  42.26 43.74 90 bottom
PR710  -  [R_0402]  21.22 83.12 0 top
PR711  -  [R_0603]  48.36 46.11 270 bottom
PR712  -  [R_0402]  21.22 84.14 0 top
PR713  -  [R0402_0OHM]  48.01 43.63 0 bottom
PR714  -  [R_0402]  18.93 80.07 0 top
PR715  -  [R_0402]  50.01 43.59 270 bottom
PR716  -  [R_0603]  26.24 67.6 270 bottom
PR717  -  [R_0402]  22.17 80.07 180 top
PR718  -  [R_0603]  29.13 80.96 180 bottom
PR719  -  [R_0402]  26.44 67.43 270 top
PR720  -  [R_0402]  21.18 71.98 90 top
PR721  -  [R_1206]  43.66 54.85 180 bottom
PR722  -  [R0402_0OHM]  21.22 79.06 0 top
PR723  -  [R_0402]  25.55 67.43 270 top
PR724  -  [R_0603]  24.22 68.31 270 top
PR725  -  [R0402_0OHM]  21.22 78.04 0 top
PR726  -  [R_0402]  23.13 70.98 0 top
PR727  -  [R0402_0OHM]  21.22 77.03 0 top
PR728  -  [R_0402]  27.63 66.29 90 bottom
PR729  -  [R0402_0OHM]  21.22 76.01 0 top
PR730  -  [R_0402]  21.22 74.99 0 bottom
PR731  -  [R0402_0OHM]  21.22 74.99 0 top
PR732  -  [R_0402]  18.93 76.01 0 top
PR733  -  [R_0402]  18.93 73.98 0 top
PR734  -  [R0402_0OHM]  31.35 73.48 270 bottom
PR735  -  [R_0402]  22.17 73.98 180 top
PR736  -  [R_0402]  31.34 73.49 270 top
PR737  -  [R_0402]  22.17 78.04 180 bottom
PR738  -  [R_0603]  33.4 82.64 180 top
PR739  -  [R_1206]  43.53 77.96 270 bottom
PR740  -  [R_0402]  22.2 71.98 90 top
PR741  -  [R_0603]  30.22 69.56 0 bottom
PR742  -  [R_0402]  28.92 71.04 0 top
PR743  -  [R_0402]  22.17 77.03 180 bottom
PR744  -  [R_0402]  28.08 72.11 180 top
PR745  -  [R_0402]  22.17 76.01 180 bottom
PR746  -  [R_0603]  28.29 68.77 0 top
PR747  -  [R_0402]  28.92 70.03 0 top
PR748  -  [R_0402]  28.09 73.97 270 top
PR749  -  [R_0402]  27.18 75.92 180 bottom
PR750  -  [R_0402]  28.21 77.76 180 bottom
PR751  -  [R_0402]  31.41 70.83 180 bottom
PR752  -  [R_0402]  27.15 73.97 270 top
PR753  -  [R_0402]  25.85 74.36 180 bottom
PR754  -  [R_0402]  26.26 72.93 270 bottom
PR755  -  [R_0603]  33.55 75.83 180 top
PR756  -  [R_1206]  43.66 66.91 270 bottom
PR757  -  [R_0402]  24.23 72.93 270 bottom
PR758  -  [R_0603]  29.92 67.09 270 bottom
PR759  -  [R_0402]  30.07 66.64 270 top
PR760  -  [R_0402]  24.86 70.81 180 bottom
PR761  -  [R_0603]  27.79 66.84 270 top
PR762  -  [R_0402]  29.06 66.64 270 top
PR763  -  [R_0402]  31.44 66.42 90 bottom
PR764  -  [R_0603]  27.15 90.25 270 top
PR765  -  [R_1206]  42.65 87.23 90 bottom
PR766  -  [R_0603]  22.2 86.63 270 bottom
PR767  -  [R_0603]  22.2 86.63 270 top
PR768  -  [R_0402]  20.93 85.44 90 top
PR769  -  [R_0402]  20.93 86.39 270 bottom
PR770  -  [R_1206]  43.53 80.63 90 bottom
PR771  -  [R_0603]  19.4 85.2 90 bottom
PR772  -  [R_0603]  17.75 85.2 90 bottom
PR773  -  [R_0402]  23.47 86.39 270 top
PR774  -  [R_0402]  23.47 85.44 90 bottom
PR775  -  [R_0603]  30.71 85.61 270 top
PR776  -  [R_0603]  33.48 88.56 90 top
PR901  -  [R_2512_4P]  6.68 91.25 90 top
PR902  -  [R0402_0OHM]  2.53 87.36 270 top
PR903  -  [R0402_0OHM]  4.93 100.36 270 top
PR904  -  [R_0402]  173.3 40.45 180 top
PR905  -  [R_0402]  172.37 39.38 270 top
PR906  -  [R_0402]  173.46 39.38 270 top
PR907  -  [R_0402]  110.24 119.7 180 top
PR908  -  [R_0402]  110.24 118.68 180 top
PR909  -  [R_0805]  183.18 35.88 180 top
PR910  -  [R0402_0OHM]  109.29 117.67 0 top
PR911  -  [R_0402]  179.39 25.97 180 top
PR912  -  [R_0402]  177.39 23.47 90 top
PR913  -  [R_0402]  169.26 33.88 90 top
PR914  -  [R_0402]  168.25 33.88 90 top
PR915  -  [R0402_0OHM]  177.39 26.01 90 top
PR916  -  [R_0402]  178.44 24.45 0 top
PR917  -  [R_0603]  178.66 37.45 90 top
PR918  -  [R_0603]  177.14 38.88 270 top
PR919  -  [R_0603]  182.55 37.66 180 top
PR920  -  [R_0402]  171.52 29.27 180 top
PR921  -  [R_0402]  170.57 31.31 0 top
PR922  -  [R_0402]  171.52 30.29 180 top
PR923  -  [R_1206_4P-D]  186.57 31.05 0 top
PR924  -  [R_0402]  170.57 26.99 0 top
PR925  -  [R_0402]  174.85 26.95 270 top
PR926  -  [R_0402]  180.98 27.75 0 top
PR927  -  [R_0402]  184.22 29.78 180 top
PR928  -  [R0402_0OHM]  184.22 28.77 180 top
PR929  -  [R_1206]  192.51 33.08 180 bottom
PR930  -  [R_0402]  229.76 22.37 180 bottom
PR931  -  [R_0402]  239.69 18.88 270 bottom
PR932  -  [R_0402]  228.81 23.38 0 bottom
PR933  -  [R_0402]  228.81 18.05 0 bottom
PR934  -  [R_0402]  228.81 17.03 0 bottom
PR935  -  [R0402_0OHM]  242.95 16.37 180 bottom
PR936  -  [R_0402]  239.73 24.91 0 bottom
PR937  -  [R_0402]  240.68 23.89 180 bottom
PR938  -  [R0402_0OHM]  228.81 16.02 0 bottom
PR939  -  [R_0402]  236.94 23.62 0 bottom
PR940  -  [R_0402]  229.76 24.4 180 bottom
PR941  -  [R_0402]  229.76 19.06 180 bottom
PR942  -  [R_0402]  231.6 15.75 0 bottom
PR943  -  [R_0402]  239.73 22.87 0 bottom
PR944  -  [R_0402]  239.49 20.05 0 bottom
PR945  -  [R_0402]  246.02 17.03 180 bottom
PR1001  -  [R_0402]  135.7 114.36 180 bottom
PR1002  -  [R0402_0OHM]  133.04 103.57 180 bottom
PR1003  -  [R_0402]  195.98 17 0 bottom
PR1004  -  [R0402_0OHM]  180.44 20.16 90 top
PR1005  -  [R_1206]  195.93 15.3 0 bottom
PR1006  -  [R0402_0OHM]  181.46 20.16 90 top
PR1007  -  [R0402_0OHM]  170.82 71.95 0 top
PR1008  -  [R0402_0OHM]  171.77 74.23 180 top
PR1009  -  [R0402_0OHM]  194.95 18.96 0 bottom
PR1010  -  [R0402_0OHM]  170.82 70.93 0 top
PR1011  -  [R_0805]  172.06 65.14 90 top
PR1012  -  [R0402_0OHM]  173.33 77.31 90 top
PR1013  -  [R_0402]  178.88 64.58 180 top
PR1014  -  [R0402_0OHM]  175.36 77.31 90 top
PR1015  -  [R0402_0OHM]  177.9 65.88 90 top
PR1016  -  [R0402_0OHM]  174.34 77.31 90 top
PR1017  -  [R0402_0OHM]  176.88 65.88 90 top
PR1018  -  [R_0402]  177.43 79.57 0 top
PR1019  -  [R0402_0OHM]  176.38 77.31 90 top
PR1020  -  [R0402_0OHM]  177.39 77.31 90 top
PR1021  -  [R0402_0OHM]  178.92 65.88 90 top
PR1022  -  [R0402_0OHM]  179.93 65.88 90 top
PR1023  -  [R0402_0OHM]  178.41 77.31 90 top
PR1024  -  [R0402_0OHM]  179.42 77.31 90 top
PR1025  -  [R0402_0OHM]  182 76.01 0 top
PR1027  -  [R0402_0OHM]  182 73.98 0 top
PR1028  -  [R_0402]  182 74.99 0 top
PR1029  -  [R0402_0OHM]  182 72.96 0 top
PU1  -  [TS5A63157DCKR_SC70-6]  2.75 75.86 0 bottom
PU2  -  [LM393DR_SO8]  174.46 168.88 180 bottom
PU101  -  [RT8205EGQW_WQFN24_4X4]  274.95 62.24 0 bottom
PU201  -  [RT8207MZQW_WQFN20_3X3]  230.5 47.03 0 bottom
PU301  -  [SY8033BDBC_DFN10_3X3]  104.69 18.32 90 bottom
PU302  -  [SY8033BDBC_DFN10_3X3]  210.08 73.55 90 bottom
PU401  -  [TPS51218DSCR_SON10_3X3]  5.71 154.69 180 top
PU501  -  [TPS51218DSCR_SON10_3X3]  58 22.85 90 bottom
PU601  -  [TPS51461RGER_QFN24_4X4]  50.63 15.87 180 bottom
PU701  -  [ISL6208BCRZ-T_QFN8_2X2]  46.35 45.14 270 bottom
PU702  -  [ISL95835HRTZ-T_TQFN40_5X5]  24.56 80.59 270 top
PU703  -  [ISL6208BCRZ-T_QFN8_2X2]  28.93 88.63 270 top
PU901  -  [BQ24745RHDR_QFN28_5X5]  173.98 32.81 270 top
PU902  -  [LM393DR_SO8]  232.29 17.4 90 bottom
PU903  -  [TC7SH08FU_SSOP5]  244.84 18.16 90 bottom
PU1001  -  [CD3301RHHR_QFN36_6X6]  174.87 69.28 0 top
PWRSW1  -  [SHORTPADS]  283.95 89.47 270 bottom
Q4  -  [SSM3K7002FU_SC70-3]  209.4 154.02 0 top
Q5  -  [SSM3K7002FU_SC70-3]  211.4 147.96 90 top
Q12  -  [FDC655BN_NL_SSOT6]  70.87 160.2 270 bottom
Q13  -  [DMN66D0LDW-7_SOT363-6]  71.87 154.05 180 bottom
Q14  -  [MMBT3904WT1G_SC70-3]  133.08 129.54 0 bottom
Q15  -  [MMBT3904WT1G_SC70-3]  123.8 59.82 180 bottom
Q16  -  [MMBT3904WT1G_SC70-3]  169.77 54.99 180 bottom
Q17  -  [MMBT3904WT1G_SC70-3]  31.36 91.52 90 bottom
Q18  -  [SI3456DDV-T1-GE3_TSOP6]  72.56 148.1 0 bottom
Q19  -  [DMN66D0LDW-7_SOT363-6]  69.51 150.29 90 bottom
Q20  -  [PDTC124EU_SC70-3]  67.41 149.58 180 bottom
Q21  -  [FDC654P-G_SSOT-6]  79.54 137.7 180 bottom
Q22  -  [SSM3K7002FU_SC70-3]  71.15 139.84 90 bottom
Q23  -  [PDTC124EU_SC70-3]  66.02 160 90 bottom
Q24  -  [PMV65XP_SOT23-3]  2.28 136.08 90 bottom
Q25  -  [SI4800BDY-T1-E3_SO8]  200.61 85.28 270 bottom
Q26  -  [MMBT3904WT1G_SC70-3]  87.48 65.78 180 top
Q27  -  [SI3456DDV-T1-GE3_TSOP6]  188.36 61.21 270 top
Q28  -  [PMST3904_SOT323-3]  150.47 165 180 top
Q29  -  [DMN66D0LDW-7_SOT363-6]  189.01 55.29 90 top
Q30  -  [SI3456DDV-T1-GE3_TSOP6]  28.99 23.74 180 bottom
Q33  -  [MMBT3904WT1G_SC70-3]  169.77 54.99 0 top
Q34  -  [SI3456DDV-T1-GE3_TSOP6]  134.92 141.1 90 top
Q36  -  [SSM3K7002FU_SC70-3]  192.89 167.13 180 top
Q38  -  [SI3456DDV-T1-GE3_TSOP6]  174.16 104.41 0 bottom
Q40  -  [SI3456DDV-T1-GE3_TSOP6]  100.89 131.7 90 top
Q44  -  [SI3456DDV-T1-GE3_TSOP6]  154.85 158.61 0 top
Q45  -  [SSM3K7002FU_SC70-3]  154.53 150.11 180 top
Q46  -  [SI3456DDV-T1-GE3_TSOP6]  12.61 150.99 0 top
Q47  -  [SSM3K7002FU_SC70-3]  177.58 147.13 90 top
Q48  -  [SSM3K7002FU_SC70-3]  147.17 172.34 0 top
Q49  -  [SI3456DDV-T1-GE3_TSOP6]  9.96 131.57 270 bottom
Q50  -  [SSM3K7002FU_SC70-3]  190.09 167.13 180 top
Q51  -  [DMN3030LSS-13_SOP8L-8]  199.87 54.21 0 bottom
Q52  -  [SSM3K7002FU_SC70-3]  179.42 151.64 180 top
Q54  -  [SI3456DDV-T1-GE3_TSOP6]  126.8 28.07 90 top
